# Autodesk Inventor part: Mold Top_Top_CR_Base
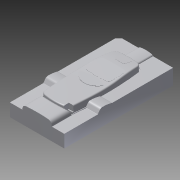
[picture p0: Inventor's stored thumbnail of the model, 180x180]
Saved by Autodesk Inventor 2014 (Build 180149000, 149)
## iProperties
Created: 2009-12
Part Number: Mold Top_Top_CR_Base
Document SubType Name: Modeling
Designer: gaom
Density: 1 g/cm^3
Material: Generic
Appearance: Default
Author: gaom
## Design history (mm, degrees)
node "Mold Top_Top_MP"
feature "Sculpt4"
feature "Solid3::Mold Top_Top_MP"
tag "TaggingFeature1"
body "Solid1"
feature "Surface4"
body "Srf4"
